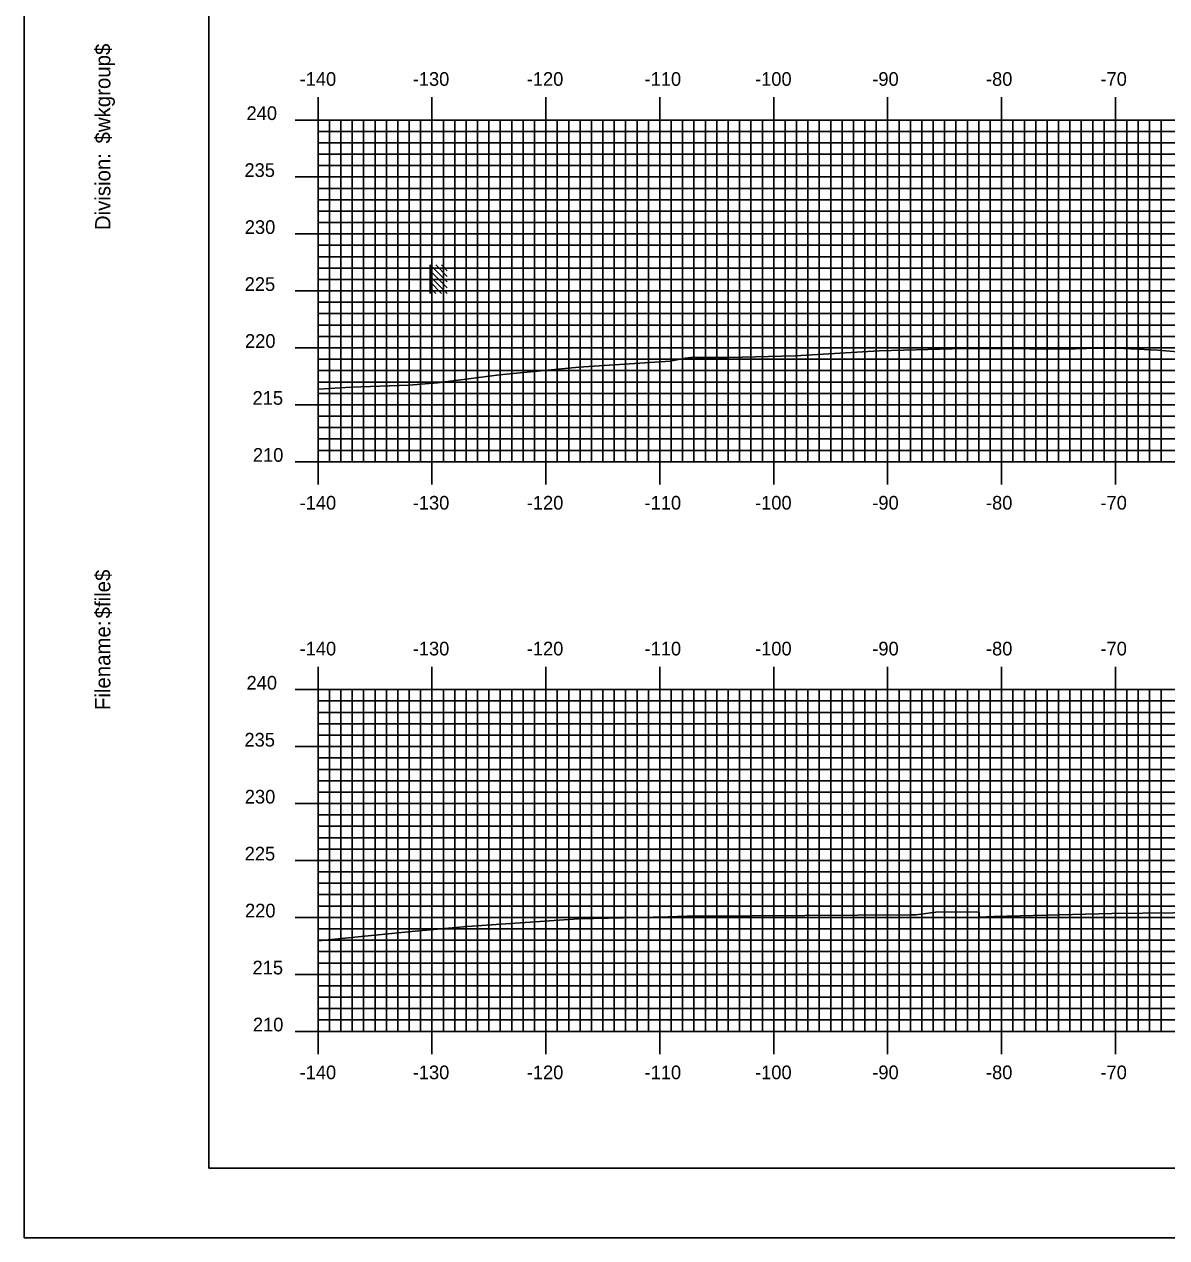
# Model space of a CAD drawing. Extents: x 850955 to 851298, y 364785 to 365005.
# Drawn here: x 850954.9 to 851055.2, y 364785.1 to 364891.6 of the extents above; entities that cross this region are included whole.
import ezdxf

# ---------------------------------------------------------------- set-up
doc = ezdxf.new("R2010")
doc.units = 0
for name, color, linetype in [('BORDER', 7, 'Continuous'), ('H_V ANNOTATION', 7, 'Continuous'), ('M_Buildings_Rooftop', 7, 'Continuous'), ('MAJOR', 7, 'Continuous'), ('MINOR', 7, 'Continuous'), ('PLOT BOUNDARY', 7, 'Continuous'), ('S_Roadway_Centerline', 7, 'Continuous')]:
    doc.layers.add(name, color=color, linetype=linetype)

msp = doc.modelspace()

# ---------------------------------------------------------------- linework, layer by layer
at = {"layer": 'BORDER'}
msp.add_lwpolyline([(850971.08, 364791.23), (851291.08, 364791.23), (851291.08, 365001.23), (850971.08, 365001.23)], close=True, dxfattribs=at)
at = {"layer": 'M_Buildings_Rooftop'}
for p, q in [((850990.51, 364867.99), (850990.51, 364870.52)), ((850992.02, 364869.01), (850990.51, 364870.52)), ((850992.02, 364869.5), (850991.03, 364870.52)), ((850992.02, 364869.99), (850991.52, 364870.52)), ((850992.02, 364868.51), (850990.51, 364869.99)), ((850992.02, 364867.99), (850990.51, 364869.5)), ((850991.52, 364867.99), (850990.51, 364869.01)), ((850991.03, 364867.99), (850990.51, 364868.51))]:
    msp.add_line(p, q, dxfattribs=at)
at = {"layer": 'MAJOR'}
for p, q in [((850980.68, 364885.24), (850980.68, 364883.23)), ((850990.68, 364885.24), (850990.68, 364883.23)), ((851000.68, 364885.24), (851000.68, 364883.23)), ((851010.68, 364885.24), (851010.68, 364883.23)), ((851020.68, 364885.24), (851020.68, 364883.23)), ((851030.68, 364885.24), (851030.68, 364883.23)), ((851040.68, 364885.24), (851040.68, 364883.23)), ((851050.68, 364885.24), (851050.68, 364883.23)), ((850978.67, 364883.23), (850980.68, 364883.23)), ((850980.68, 364883.23), (851260.68, 364883.23)), ((850980.68, 364853.23), (850980.68, 364883.23)), ((850980.68, 364853.23), (850980.68, 364883.23)), ((850980.68, 364883.23), (851260.68, 364883.23)), ((850990.68, 364853.23), (850990.68, 364883.23)), ((851000.68, 364853.23), (851000.68, 364883.23)), ((851010.68, 364853.23), (851010.68, 364883.23)), ((851020.68, 364853.23), (851020.68, 364883.23)), ((851030.68, 364853.23), (851030.68, 364883.23)), ((851040.68, 364853.23), (851040.68, 364883.23)), ((851050.68, 364853.23), (851050.68, 364883.23)), ((850978.67, 364878.23), (850980.68, 364878.23)), ((850980.68, 364878.23), (851260.68, 364878.23)), ((850978.67, 364873.23), (850980.68, 364873.23)), ((850980.68, 364873.23), (851260.68, 364873.23)), ((850978.67, 364868.23), (850980.68, 364868.23)), ((850980.68, 364868.23), (851260.68, 364868.23)), ((850978.67, 364863.23), (850980.68, 364863.23)), ((850980.68, 364863.23), (851260.68, 364863.23)), ((850978.67, 364858.23), (850980.68, 364858.23)), ((850980.68, 364858.23), (851260.68, 364858.23)), ((850978.67, 364853.23), (850980.68, 364853.23)), ((850980.68, 364853.23), (851260.68, 364853.23)), ((850980.68, 364853.23), (851260.68, 364853.23)), ((850980.68, 364851.23), (850980.68, 364853.23)), ((850990.68, 364851.23), (850990.68, 364853.23)), ((851000.68, 364851.23), (851000.68, 364853.23)), ((851010.68, 364851.23), (851010.68, 364853.23)), ((851020.68, 364851.23), (851020.68, 364853.23)), ((851030.68, 364851.23), (851030.68, 364853.23)), ((851040.68, 364851.23), (851040.68, 364853.23)), ((851050.68, 364851.23), (851050.68, 364853.23)), ((850980.68, 364835.24), (850980.68, 364833.23)), ((850990.68, 364835.24), (850990.68, 364833.23)), ((851000.68, 364835.24), (851000.68, 364833.23)), ((851010.68, 364835.24), (851010.68, 364833.23)), ((851020.68, 364835.24), (851020.68, 364833.23)), ((851030.68, 364835.24), (851030.68, 364833.23)), ((851040.68, 364835.24), (851040.68, 364833.23)), ((851050.68, 364835.24), (851050.68, 364833.23)), ((850978.67, 364833.23), (850980.68, 364833.23)), ((850980.68, 364833.23), (851260.68, 364833.23)), ((850980.68, 364803.23), (850980.68, 364833.23)), ((850980.68, 364803.23), (850980.68, 364833.23)), ((850980.68, 364833.23), (851260.68, 364833.23)), ((850990.68, 364803.23), (850990.68, 364833.23)), ((851000.68, 364803.23), (851000.68, 364833.23)), ((851010.68, 364803.23), (851010.68, 364833.23)), ((851020.68, 364803.23), (851020.68, 364833.23)), ((851030.68, 364803.23), (851030.68, 364833.23)), ((851040.68, 364803.23), (851040.68, 364833.23)), ((851050.68, 364803.23), (851050.68, 364833.23)), ((850978.67, 364828.23), (850980.68, 364828.23)), ((850980.68, 364828.23), (851260.68, 364828.23)), ((850978.67, 364823.23), (850980.68, 364823.23)), ((850980.68, 364823.23), (851260.68, 364823.23)), ((850978.67, 364818.23), (850980.68, 364818.23)), ((850980.68, 364818.23), (851260.68, 364818.23)), ((850978.67, 364813.23), (850980.68, 364813.23)), ((850980.68, 364813.23), (851260.68, 364813.23)), ((850978.67, 364808.23), (850980.68, 364808.23)), ((850980.68, 364808.23), (851260.68, 364808.23)), ((850978.67, 364803.23), (850980.68, 364803.23)), ((850980.68, 364803.23), (851260.68, 364803.23)), ((850980.68, 364803.23), (851260.68, 364803.23)), ((850980.68, 364801.23), (850980.68, 364803.23)), ((850990.68, 364801.23), (850990.68, 364803.23)), ((851000.68, 364801.23), (851000.68, 364803.23)), ((851010.68, 364801.23), (851010.68, 364803.23)), ((851020.68, 364801.23), (851020.68, 364803.23)), ((851030.68, 364801.23), (851030.68, 364803.23)), ((851040.68, 364801.23), (851040.68, 364803.23)), ((851050.68, 364801.23), (851050.68, 364803.23))]:
    msp.add_line(p, q, dxfattribs=at)
at = {"layer": 'MINOR'}
for p, q in [((850981.68, 364853.23), (850981.68, 364883.23)), ((850982.68, 364853.23), (850982.68, 364883.23)), ((850983.68, 364853.23), (850983.68, 364883.23)), ((850984.68, 364853.23), (850984.68, 364883.23)), ((850985.68, 364853.23), (850985.68, 364883.23)), ((850986.68, 364853.23), (850986.68, 364883.23)), ((850987.68, 364853.23), (850987.68, 364883.23)), ((850988.68, 364853.23), (850988.68, 364883.23)), ((850989.68, 364853.23), (850989.68, 364883.23)), ((850991.68, 364853.23), (850991.68, 364883.23)), ((850992.68, 364853.23), (850992.68, 364883.23)), ((850993.68, 364853.23), (850993.68, 364883.23)), ((850994.68, 364853.23), (850994.68, 364883.23)), ((850995.68, 364853.23), (850995.68, 364883.23)), ((850996.68, 364853.23), (850996.68, 364883.23)), ((850997.68, 364853.23), (850997.68, 364883.23)), ((850998.68, 364853.23), (850998.68, 364883.23)), ((850999.68, 364853.23), (850999.68, 364883.23)), ((851001.68, 364853.23), (851001.68, 364883.23)), ((851002.68, 364853.23), (851002.68, 364883.23)), ((851003.68, 364853.23), (851003.68, 364883.23)), ((851004.68, 364853.23), (851004.68, 364883.23)), ((851005.68, 364853.23), (851005.68, 364883.23)), ((851006.68, 364853.23), (851006.68, 364883.23)), ((851007.68, 364853.23), (851007.68, 364883.23)), ((851008.68, 364853.23), (851008.68, 364883.23)), ((851009.68, 364853.23), (851009.68, 364883.23)), ((851011.68, 364853.23), (851011.68, 364883.23)), ((851012.68, 364853.23), (851012.68, 364883.23)), ((851013.68, 364853.23), (851013.68, 364883.23)), ((851014.68, 364853.23), (851014.68, 364883.23)), ((851015.68, 364853.23), (851015.68, 364883.23)), ((851016.68, 364853.23), (851016.68, 364883.23)), ((851017.68, 364853.23), (851017.68, 364883.23)), ((851018.68, 364853.23), (851018.68, 364883.23)), ((851019.68, 364853.23), (851019.68, 364883.23)), ((851021.68, 364853.23), (851021.68, 364883.23)), ((851022.68, 364853.23), (851022.68, 364883.23)), ((851023.68, 364853.23), (851023.68, 364883.23)), ((851024.68, 364853.23), (851024.68, 364883.23)), ((851025.68, 364853.23), (851025.68, 364883.23)), ((851026.68, 364853.23), (851026.68, 364883.23)), ((851027.68, 364853.23), (851027.68, 364883.23)), ((851028.68, 364853.23), (851028.68, 364883.23)), ((851029.68, 364853.23), (851029.68, 364883.23)), ((851031.68, 364853.23), (851031.68, 364883.23)), ((851032.68, 364853.23), (851032.68, 364883.23)), ((851033.68, 364853.23), (851033.68, 364883.23)), ((851034.68, 364853.23), (851034.68, 364883.23)), ((851035.68, 364853.23), (851035.68, 364883.23)), ((851036.68, 364853.23), (851036.68, 364883.23)), ((851037.68, 364853.23), (851037.68, 364883.23)), ((851038.68, 364853.23), (851038.68, 364883.23)), ((851039.68, 364853.23), (851039.68, 364883.23)), ((851041.68, 364853.23), (851041.68, 364883.23)), ((851042.68, 364853.23), (851042.68, 364883.23)), ((851043.68, 364853.23), (851043.68, 364883.23)), ((851044.68, 364853.23), (851044.68, 364883.23)), ((851045.68, 364853.23), (851045.68, 364883.23)), ((851046.68, 364853.23), (851046.68, 364883.23)), ((851047.68, 364853.23), (851047.68, 364883.23)), ((851048.68, 364853.23), (851048.68, 364883.23)), ((851049.68, 364853.23), (851049.68, 364883.23)), ((851051.68, 364853.23), (851051.68, 364883.23)), ((851052.68, 364853.23), (851052.68, 364883.23)), ((851053.68, 364853.23), (851053.68, 364883.23)), ((851054.68, 364853.23), (851054.68, 364883.23)), ((850980.68, 364882.23), (851260.68, 364882.23)), ((850980.68, 364882.23), (850982.68, 364882.23)), ((850980.68, 364881.23), (851260.68, 364881.23)), ((850980.68, 364881.23), (850982.68, 364881.23)), ((850980.68, 364880.23), (851260.68, 364880.23)), ((850980.68, 364880.23), (850982.68, 364880.23)), ((850980.68, 364879.23), (851260.68, 364879.23)), ((850980.68, 364879.23), (850982.68, 364879.23)), ((850980.68, 364877.23), (851260.68, 364877.23)), ((850980.68, 364877.23), (850982.68, 364877.23)), ((850980.68, 364876.23), (851260.68, 364876.23)), ((850980.68, 364876.23), (850982.68, 364876.23)), ((850980.68, 364875.23), (851260.68, 364875.23)), ((850980.68, 364875.23), (850982.68, 364875.23)), ((850980.68, 364874.23), (851260.68, 364874.23)), ((850980.68, 364874.23), (850982.68, 364874.23)), ((850980.68, 364872.23), (851260.68, 364872.23)), ((850980.68, 364872.23), (850982.68, 364872.23)), ((850980.68, 364871.23), (851260.68, 364871.23)), ((850980.68, 364871.23), (850982.68, 364871.23)), ((850980.68, 364870.23), (851260.68, 364870.23)), ((850980.68, 364870.23), (850982.68, 364870.23)), ((850980.68, 364869.23), (851260.68, 364869.23)), ((850980.68, 364869.23), (850982.68, 364869.23)), ((850980.68, 364867.23), (851260.68, 364867.23)), ((850980.68, 364867.23), (850982.68, 364867.23)), ((850980.68, 364866.23), (851260.68, 364866.23)), ((850980.68, 364866.23), (850982.68, 364866.23)), ((850980.68, 364865.23), (851260.68, 364865.23)), ((850980.68, 364865.23), (850982.68, 364865.23)), ((850980.68, 364864.23), (851260.68, 364864.23)), ((850980.68, 364864.23), (850982.68, 364864.23)), ((850980.68, 364862.23), (851260.68, 364862.23)), ((850980.68, 364862.23), (850982.68, 364862.23)), ((850980.68, 364861.23), (851260.68, 364861.23)), ((850980.68, 364861.23), (850982.68, 364861.23)), ((850980.68, 364860.23), (851260.68, 364860.23)), ((850980.68, 364860.23), (850982.68, 364860.23)), ((850980.68, 364859.23), (851260.68, 364859.23)), ((850980.68, 364859.23), (850982.68, 364859.23)), ((850980.68, 364857.23), (851260.68, 364857.23)), ((850980.68, 364857.23), (850982.68, 364857.23)), ((850980.68, 364856.23), (851260.68, 364856.23)), ((850980.68, 364856.23), (850982.68, 364856.23)), ((850980.68, 364855.23), (851260.68, 364855.23)), ((850980.68, 364855.23), (850982.68, 364855.23)), ((850980.68, 364854.23), (851260.68, 364854.23)), ((850980.68, 364854.23), (850982.68, 364854.23)), ((850981.68, 364803.23), (850981.68, 364833.23)), ((850982.68, 364803.23), (850982.68, 364833.23)), ((850983.68, 364803.23), (850983.68, 364833.23)), ((850984.68, 364803.23), (850984.68, 364833.23)), ((850985.68, 364803.23), (850985.68, 364833.23)), ((850986.68, 364803.23), (850986.68, 364833.23)), ((850987.68, 364803.23), (850987.68, 364833.23)), ((850988.68, 364803.23), (850988.68, 364833.23)), ((850989.68, 364803.23), (850989.68, 364833.23)), ((850991.68, 364803.23), (850991.68, 364833.23)), ((850992.68, 364803.23), (850992.68, 364833.23)), ((850993.68, 364803.23), (850993.68, 364833.23)), ((850994.68, 364803.23), (850994.68, 364833.23)), ((850995.68, 364803.23), (850995.68, 364833.23)), ((850996.68, 364803.23), (850996.68, 364833.23)), ((850997.68, 364803.23), (850997.68, 364833.23)), ((850998.68, 364803.23), (850998.68, 364833.23)), ((850999.68, 364803.23), (850999.68, 364833.23)), ((851001.68, 364803.23), (851001.68, 364833.23)), ((851002.68, 364803.23), (851002.68, 364833.23)), ((851003.68, 364803.23), (851003.68, 364833.23)), ((851004.68, 364803.23), (851004.68, 364833.23)), ((851005.68, 364803.23), (851005.68, 364833.23)), ((851006.68, 364803.23), (851006.68, 364833.23)), ((851007.68, 364803.23), (851007.68, 364833.23)), ((851008.68, 364803.23), (851008.68, 364833.23)), ((851009.68, 364803.23), (851009.68, 364833.23)), ((851011.68, 364803.23), (851011.68, 364833.23)), ((851012.68, 364803.23), (851012.68, 364833.23)), ((851013.68, 364803.23), (851013.68, 364833.23)), ((851014.68, 364803.23), (851014.68, 364833.23)), ((851015.68, 364803.23), (851015.68, 364833.23)), ((851016.68, 364803.23), (851016.68, 364833.23)), ((851017.68, 364803.23), (851017.68, 364833.23)), ((851018.68, 364803.23), (851018.68, 364833.23)), ((851019.68, 364803.23), (851019.68, 364833.23)), ((851021.68, 364803.23), (851021.68, 364833.23)), ((851022.68, 364803.23), (851022.68, 364833.23)), ((851023.68, 364803.23), (851023.68, 364833.23)), ((851024.68, 364803.23), (851024.68, 364833.23)), ((851025.68, 364803.23), (851025.68, 364833.23)), ((851026.68, 364803.23), (851026.68, 364833.23)), ((851027.68, 364803.23), (851027.68, 364833.23)), ((851028.68, 364803.23), (851028.68, 364833.23)), ((851029.68, 364803.23), (851029.68, 364833.23)), ((851031.68, 364803.23), (851031.68, 364833.23)), ((851032.68, 364803.23), (851032.68, 364833.23)), ((851033.68, 364803.23), (851033.68, 364833.23)), ((851034.68, 364803.23), (851034.68, 364833.23)), ((851035.68, 364803.23), (851035.68, 364833.23)), ((851036.68, 364803.23), (851036.68, 364833.23)), ((851037.68, 364803.23), (851037.68, 364833.23)), ((851038.68, 364803.23), (851038.68, 364833.23)), ((851039.68, 364803.23), (851039.68, 364833.23)), ((851041.68, 364803.23), (851041.68, 364833.23)), ((851042.68, 364803.23), (851042.68, 364833.23)), ((851043.68, 364803.23), (851043.68, 364833.23)), ((851044.68, 364803.23), (851044.68, 364833.23)), ((851045.68, 364803.23), (851045.68, 364833.23)), ((851046.68, 364803.23), (851046.68, 364833.23)), ((851047.68, 364803.23), (851047.68, 364833.23)), ((851048.68, 364803.23), (851048.68, 364833.23)), ((851049.68, 364803.23), (851049.68, 364833.23)), ((851051.68, 364803.23), (851051.68, 364833.23)), ((851052.68, 364803.23), (851052.68, 364833.23)), ((851053.68, 364803.23), (851053.68, 364833.23)), ((851054.68, 364803.23), (851054.68, 364833.23)), ((850980.68, 364832.23), (851260.68, 364832.23)), ((850980.68, 364832.23), (850982.68, 364832.23)), ((850980.68, 364831.23), (851260.68, 364831.23)), ((850980.68, 364831.23), (850982.68, 364831.23)), ((850980.68, 364830.23), (851260.68, 364830.23)), ((850980.68, 364830.23), (850982.68, 364830.23)), ((850980.68, 364829.23), (851260.68, 364829.23)), ((850980.68, 364829.23), (850982.68, 364829.23)), ((850980.68, 364827.23), (851260.68, 364827.23)), ((850980.68, 364827.23), (850982.68, 364827.23)), ((850980.68, 364826.23), (851260.68, 364826.23)), ((850980.68, 364826.23), (850982.68, 364826.23)), ((850980.68, 364825.23), (851260.68, 364825.23)), ((850980.68, 364825.23), (850982.68, 364825.23)), ((850980.68, 364824.23), (851260.68, 364824.23)), ((850980.68, 364824.23), (850982.68, 364824.23)), ((850980.68, 364822.23), (851260.68, 364822.23)), ((850980.68, 364822.23), (850982.68, 364822.23)), ((850980.68, 364821.23), (851260.68, 364821.23)), ((850980.68, 364821.23), (850982.68, 364821.23)), ((850980.68, 364820.23), (851260.68, 364820.23)), ((850980.68, 364820.23), (850982.68, 364820.23)), ((850980.68, 364819.23), (851260.68, 364819.23)), ((850980.68, 364819.23), (850982.68, 364819.23)), ((850980.68, 364817.23), (851260.68, 364817.23)), ((850980.68, 364817.23), (850982.68, 364817.23)), ((850980.68, 364816.23), (851260.68, 364816.23)), ((850980.68, 364816.23), (850982.68, 364816.23)), ((850980.68, 364815.23), (851260.68, 364815.23)), ((850980.68, 364815.23), (850982.68, 364815.23)), ((850980.68, 364814.23), (851260.68, 364814.23)), ((850980.68, 364814.23), (850982.68, 364814.23)), ((850980.68, 364812.23), (851260.68, 364812.23)), ((850980.68, 364812.23), (850982.68, 364812.23)), ((850980.68, 364811.23), (851260.68, 364811.23)), ((850980.68, 364811.23), (850982.68, 364811.23)), ((850980.68, 364810.23), (851260.68, 364810.23)), ((850980.68, 364810.23), (850982.68, 364810.23)), ((850980.68, 364809.23), (851260.68, 364809.23)), ((850980.68, 364809.23), (850982.68, 364809.23)), ((850980.68, 364807.23), (851260.68, 364807.23)), ((850980.68, 364807.23), (850982.68, 364807.23)), ((850980.68, 364806.23), (851260.68, 364806.23)), ((850980.68, 364806.23), (850982.68, 364806.23)), ((850980.68, 364805.23), (851260.68, 364805.23)), ((850980.68, 364805.23), (850982.68, 364805.23)), ((850980.68, 364804.23), (851260.68, 364804.23)), ((850980.68, 364804.23), (850982.68, 364804.23))]:
    msp.add_line(p, q, dxfattribs=at)
at = {"layer": 'PLOT BOUNDARY'}
msp.add_lwpolyline([(850954.89, 364785.11), (851294.89, 364785.11), (851294.89, 365005.11), (850954.89, 365005.11)], close=True, dxfattribs=at)
at = {"layer": 'S_Roadway_Centerline'}
for points in [[(850980.68, 364859.59), (850983.58, 364859.78), (850988.66, 364859.94), (850991.18, 364860.15), (850996.62, 364860.86), (851003.57, 364861.54), (851011.58, 364862.05), (851012.93, 364862.33), (851013.36, 364862.37), (851016.75, 364862.39), (851022.55, 364862.54), (851029.95, 364862.97), (851036.35, 364863.14), (851036.98, 364863.16), (851040.03, 364863.18), (851046.24, 364863.12), (851048.14, 364863.18), (851050.83, 364863.2), (851054.36, 364863.04), (851058.28, 364862.7)], [(850980.68, 364811.18), (850988.89, 364812.01), (850993.77, 364812.42), (851003.55, 364813.1), (851011.41, 364813.29), (851013.06, 364813.35), (851013.14, 364813.35), (851014.17, 364813.35), (851032.7, 364813.45), (851033.09, 364813.46), (851033.16, 364813.46), (851034.91, 364813.7), (851035.69, 364813.71), (851038.71, 364813.69), (851038.71, 364813.6), (851038.71, 364813.26), (851040.01, 364813.32), (851050.35, 364813.57), (851061.18, 364813.68)]]:
    msp.add_lwpolyline(points, dxfattribs=at)

# ---------------------------------------------------------------- texts
at = {"layer": 'BORDER'}
for s, p in [('$wkgroup$', (850962.45, 364881.17)), ('Division:', (850962.45, 364873.56)), ('$file$', (850962.45, 364839.48)), ('Filename:', (850962.45, 364831.43))]:
    msp.add_text(s, height=1.339, rotation=90, dxfattribs=at).set_placement(p)
at = {"layer": 'H_V ANNOTATION'}
for s, p in [('-140', (850979.06, 364886.23)), ('-130', (850988.99, 364886.23)), ('-120', (850999, 364886.23)), ('-110', (851009.34, 364886.23)), ('-100', (851019.04, 364886.23)), ('-90', (851029.33, 364886.23)), ('-80', (851039.31, 364886.23)), ('-70', (851049.36, 364886.23)), ('240', (850974.4, 364883.23)), ('235', (850974.22, 364878.23)), ('230', (850974.25, 364873.23)), ('225', (850974.24, 364868.23)), ('220', (850974.27, 364863.23)), ('215', (850974.93, 364858.23)), ('210', (850974.96, 364853.23)), ('-140', (850979.06, 364849.03)), ('-130', (850988.99, 364849.03)), ('-120', (850999, 364849.03)), ('-110', (851009.34, 364849.03)), ('-100', (851019.04, 364849.03)), ('-90', (851029.33, 364849.03)), ('-80', (851039.31, 364849.03)), ('-70', (851049.36, 364849.03)), ('-140', (850979.06, 364836.23)), ('-130', (850988.99, 364836.23)), ('-120', (850999, 364836.23)), ('-110', (851009.34, 364836.23)), ('-100', (851019.04, 364836.23)), ('-90', (851029.33, 364836.23)), ('-80', (851039.31, 364836.23)), ('-70', (851049.36, 364836.23)), ('240', (850974.4, 364833.23)), ('235', (850974.22, 364828.23)), ('230', (850974.25, 364823.23)), ('225', (850974.24, 364818.23)), ('220', (850974.27, 364813.23)), ('215', (850974.93, 364808.23)), ('210', (850974.96, 364803.23)), ('-140', (850979.06, 364799.03)), ('-130', (850988.99, 364799.03)), ('-120', (850999, 364799.03)), ('-110', (851009.34, 364799.03)), ('-100', (851019.04, 364799.03)), ('-90', (851029.33, 364799.03)), ('-80', (851039.31, 364799.03)), ('-70', (851049.36, 364799.03))]:
    msp.add_text(s, height=1.2, dxfattribs=at).set_placement(p)
at = {"layer": 'MAJOR'}
for p in [(850980.67, 364853.23), (850980.67, 364803.23)]:
    msp.add_text('-', height=0.012, dxfattribs=at).set_placement(p)

doc.saveas('drawing.dxf')
